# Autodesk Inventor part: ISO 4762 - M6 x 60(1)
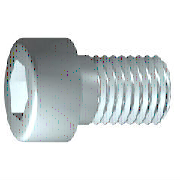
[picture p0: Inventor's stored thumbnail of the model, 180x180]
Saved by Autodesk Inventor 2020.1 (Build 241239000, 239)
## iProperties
Created: 2019-01
Part Number: ISO 4762 - M6 x 60(1)
Material: Edelstahl, 440C
Description: Innensechskantschraube
Document SubType Name: Modeling
Standard: ISO 4762
Designer: lutzd
Standard Revision: Fourth edition 2004-03-01
Standards Organization: ISO
Language: de-DE
Size Designation: M6 x 60
Categories: <MemberInstance><Categories><Category DisplayName="Verbindungselemente" InternalName="e4da775c-781d-43d5-af7c-5136215cf5a6" Mnemonic="FSTN"><Category DisplayNam
Mass: 16.1431 g
Surface Area: 15.1808 cm^2
Volume: 2.08298 cm^3
Density: 7.75 g/cm^3
Appearance: Halbpoliert
IsCustomPart: 0
Author: lutzd
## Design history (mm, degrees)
body "Solid1"
sketch "Skizze1"
  geometry: L1 (-1.333, 0)-(60, 0); L2 (60, 0)-(60, 3); L3 (60, 3)-(36, 3); L4 (36, 3)-(35.386, 3); L5 (35.386, 3)-(0, 3); L6 (0, 3)-(0, 5); L7 (0, 5)-(-6, 5); L8 (-6, 5)-(-6, 2.887); L9 (-6, 2.887)-(-3, 2.887); L10 (-3, 2.887)-(-1.333, 0); L11 (-19.2, 0)-(73.2, 0) reference; L12 (0, -1)-(0, 6) reference; L13 (36, 3)-(0, 3)
  constraints: 22 end point, 6 parallel, 2 collinear, 2 perpendicular, 1 horizontal, 1 point on line
  dimensions: "d1" = 24 distance from line of L3.end L2 (= GEL); "d2" = 0.61355 distance of L4.end L3.end (computed from GAL); "d3" = 6 distance between parallel lines of L8 L6 (= KOH); "d4" = 3 distance of L8.end L9.end (= INTI); "d5" = 60 deg angle of L10 L1; "d6" = 6 diameter of L3 L1 (= GD); "d7" = 6 diameter of L5 L1 (= BDM); "d8" = 5.7735 diameter of L9 L1 (= 1.1547 x SW); "d9" = 10 diameter of L7 L1 (= KOD); "d26" = 60 distance between parallel lines of L12 L2 (= NLG)
workplane "Work Plane1"
fillet "Fillet2" dims "d30" = 0.1 (= R)
revolve "Körper" stored, may be unused: angle "d10" = 90 deg
sketch "Skizze2"
  geometry: L1 (0, -7)-(0, 7) reference; L2 (-7, 0)-(7, 0) reference; L3 (2.887, 0)-(1.443, -2.5); L4 (1.443, -2.5)-(-1.443, -2.5); L5 (-1.443, -2.5)-(-2.887, 0); L6 (-2.887, 0)-(-1.443, 2.5); L7 (-1.443, 2.5)-(1.443, 2.5); L8 (1.443, 2.5)-(2.887, 0); 2 further points
  constraints: 12 end point, 1 coincident, 1 horizontal alignment, 1 point on line, 12 other
extrude "Loch" join sketch "Skizze2" stored distance "d11" = 10; taper "d12" = 0 deg
fillet "Rundung1" dims "d17" = 0.6 (= RR)
feature "Gewinde" dims "d13" = 24 (= GEL), "d14" = 0
chamfer "Fase1" distance "d15" = 0.61345 (= -0.5 x SPD + 0.5 x GD); stored, may be unused: second distance "d16" = 0.61345 (= GUL), angle "d27" = 45 deg
other parameters: "GD" = 6 [user parameter; used in 2 equation terms], "NLG" = 60 [user parameter; used in 1 equation term], "GEL" = 24 [user parameter; used in 2 equation terms], "KOD" = 10 [user parameter; used in 1 equation term], "KOH" = 6 [user parameter; used in 1 equation term], "INTI" = 3 [user parameter; used in 1 equation term], "GAL" = 0.61345 (= 0.61345 x PTC) [user parameter; used in 1 equation term], "GUL" = 0.61345 (= 0.61345 x PTC) [user parameter; used in 1 equation term], "BDM" = 6 (= NND) [user parameter; used in 1 equation term], "SW" = 5 [user parameter; used in 2 equation terms], "RR" = 0.6 [user parameter; used in 1 equation term], "SPD" = 4.7731 (= NND - 1.2269 x PTC) [user parameter; used in 1 equation term], "d19" = 0, "d28" = 0, "d29" = 0, "R" = 0.1 [user parameter; used in 1 equation term], "TOA" = 30 deg [user parameter], "GD1" = 4.7731 (= THREADDIA - 1.2269 x PTC) [user parameter], "THREADDIA" = 6 [user parameter; used in 1 equation term], "FAWI" = 45 deg [user parameter], "PTC" = 1 [user parameter; used in 5 equation terms], "NND" = 6 [user parameter; used in 2 equation terms], "E0" = 5.775 (= 1.155 x SW) [user parameter]
